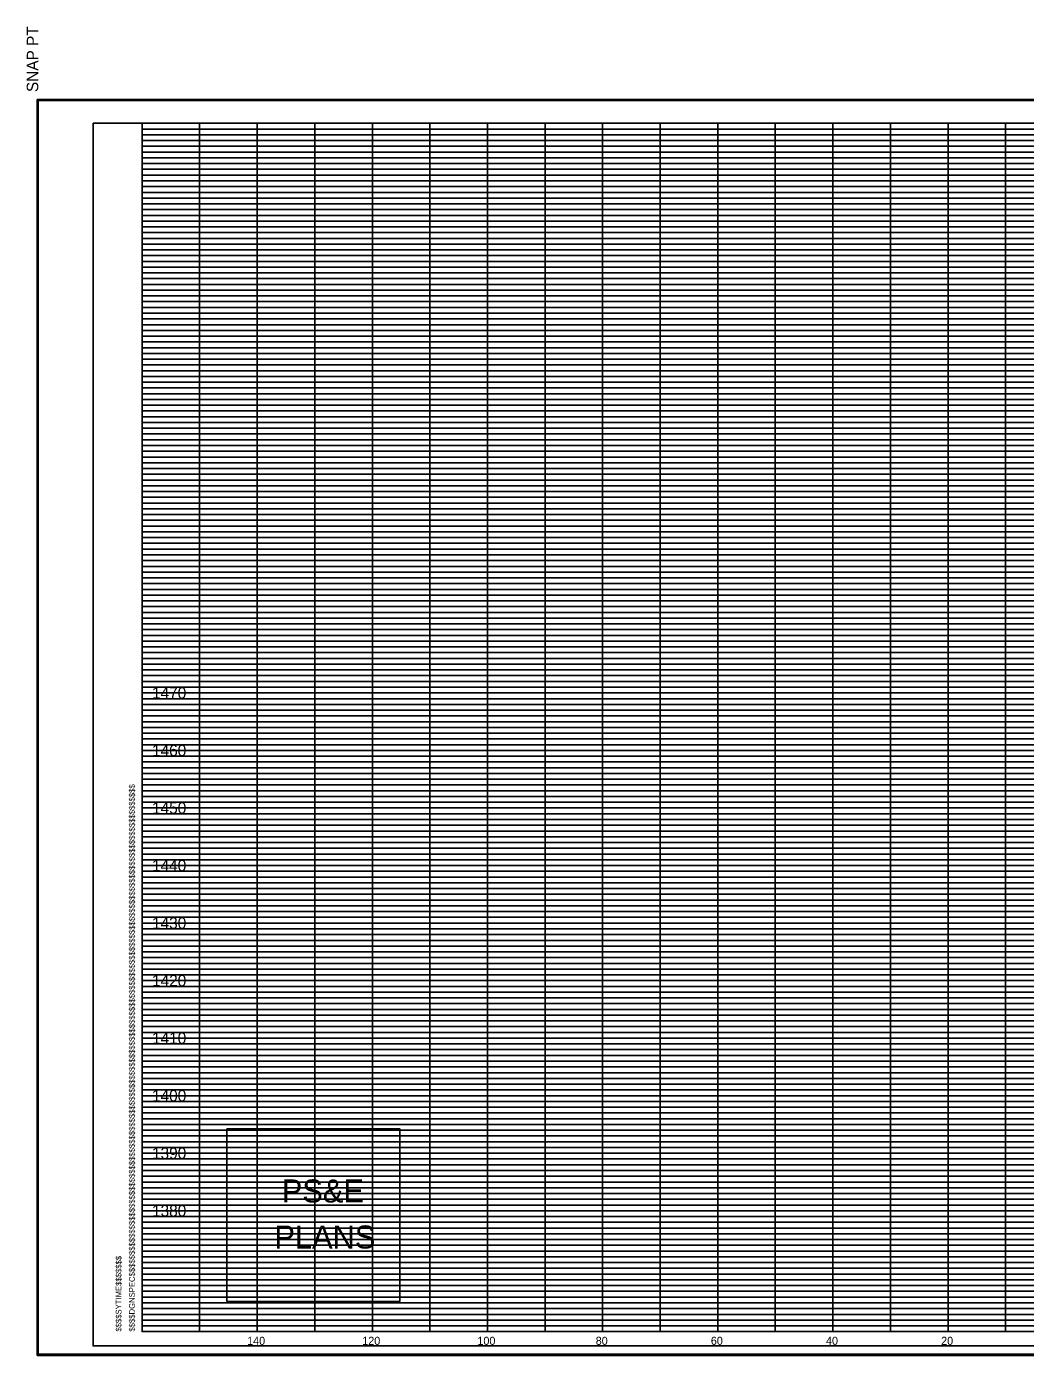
# Model space of a CAD drawing. Extents: x 980 to 2064, y 978 to 2267.
# Drawn here: x 1719.9 to 1893.4, y 1515.9 to 1746.8 of the extents above; entities that cross this region are included whole.
import ezdxf

# ---------------------------------------------------------------- set-up
doc = ezdxf.new("R2010")
doc.units = 0
for name, color, linetype in [('Default', 7, 'Continuous'), ('DESIGN - SHEET - Corner Text', 7, 'Continuous'), ('DESIGN - SHEET - Light Grid', 7, 'Continuous'), ('DESIGN - SHEET - Linework', 7, 'Continuous'), ('DESIGN - SHEET - Plot Shape', 7, 'Continuous')]:
    doc.layers.add(name, color=color, linetype=linetype)

# ---------------------------------------------------------------- blocks, each defined once
blk = doc.blocks.new('XSTSHT')
at = {"layer": 'DESIGN - SHEET - Light Grid'}
for p, q in [((0, 20.9), (8, 20.9)), ((0, 20.8), (8, 20.8)), ((8, 20.9), (16, 20.9)), ((8, 20.8), (16, 20.8)), ((0, 20.7), (8, 20.7)), ((0, 20.6), (8, 20.6)), ((8, 20.7), (16, 20.7)), ((8, 20.6), (16, 20.6)), ((0, 20.5), (8, 20.5)), ((0, 20.4), (8, 20.4)), ((8, 20.5), (16, 20.5)), ((8, 20.4), (16, 20.4)), ((0, 20.3), (8, 20.3)), ((0, 20.2), (8, 20.2)), ((0, 20.1), (8, 20.1)), ((8, 20.3), (16, 20.3)), ((8, 20.2), (16, 20.2)), ((8, 20.1), (16, 20.1)), ((0, 19.9), (8, 19.9)), ((8, 19.9), (16, 19.9)), ((0, 19.8), (8, 19.8)), ((0, 19.7), (8, 19.7)), ((8, 19.8), (16, 19.8)), ((8, 19.7), (16, 19.7)), ((0, 19.6), (8, 19.6)), ((0, 19.5), (8, 19.5)), ((0, 19.4), (8, 19.4)), ((8, 19.6), (16, 19.6)), ((8, 19.5), (16, 19.5)), ((8, 19.4), (16, 19.4)), ((0, 19.3), (8, 19.3)), ((0, 19.2), (8, 19.2)), ((8, 19.3), (16, 19.3)), ((8, 19.2), (16, 19.2)), ((0, 19.1), (8, 19.1)), ((8, 19.1), (16, 19.1)), ((0, 18.9), (8, 18.9)), ((0, 18.8), (8, 18.8)), ((8, 18.9), (16, 18.9)), ((8, 18.8), (16, 18.8)), ((0, 18.7), (8, 18.7)), ((0, 18.6), (8, 18.6)), ((0, 18.5), (8, 18.5)), ((8, 18.7), (16, 18.7)), ((8, 18.6), (16, 18.6)), ((8, 18.5), (16, 18.5)), ((0, 18.4), (8, 18.4)), ((0, 18.3), (8, 18.3)), ((8, 18.4), (16, 18.4)), ((8, 18.3), (16, 18.3)), ((0, 18.2), (8, 18.2)), ((0, 18.1), (8, 18.1)), ((8, 18.2), (16, 18.2)), ((8, 18.1), (16, 18.1)), ((0, 17.9), (8, 17.9)), ((0, 17.8), (8, 17.8)), ((8, 17.9), (16, 17.9)), ((8, 17.8), (16, 17.8)), ((0, 17.7), (8, 17.7)), ((0, 17.6), (8, 17.6)), ((8, 17.7), (16, 17.7)), ((8, 17.6), (16, 17.6)), ((0, 17.5), (8, 17.5)), ((0, 17.4), (8, 17.4)), ((8, 17.5), (16, 17.5)), ((8, 17.4), (16, 17.4)), ((0, 17.3), (8, 17.3)), ((0, 17.2), (8, 17.2)), ((0, 17.1), (8, 17.1)), ((8, 17.3), (16, 17.3)), ((8, 17.2), (16, 17.2)), ((8, 17.1), (16, 17.1)), ((0, 16.9), (8, 16.9)), ((8, 16.9), (16, 16.9)), ((0, 16.8), (8, 16.8)), ((0, 16.7), (8, 16.7)), ((8, 16.8), (16, 16.8)), ((8, 16.7), (16, 16.7)), ((0, 16.6), (8, 16.6)), ((0, 16.5), (8, 16.5)), ((0, 16.4), (8, 16.4)), ((8, 16.6), (16, 16.6)), ((8, 16.5), (16, 16.5)), ((8, 16.4), (16, 16.4)), ((0, 16.3), (8, 16.3)), ((0, 16.2), (8, 16.2)), ((8, 16.3), (16, 16.3)), ((8, 16.2), (16, 16.2)), ((0, 16.1), (8, 16.1)), ((8, 16.1), (16, 16.1)), ((0, 15.9), (8, 15.9)), ((0, 15.8), (8, 15.8)), ((8, 15.9), (16, 15.9)), ((8, 15.8), (16, 15.8)), ((0, 15.7), (8, 15.7)), ((0, 15.6), (8, 15.6)), ((0, 15.5), (8, 15.5)), ((8, 15.7), (16, 15.7)), ((8, 15.6), (16, 15.6)), ((8, 15.5), (16, 15.5)), ((0, 15.4), (8, 15.4)), ((0, 15.3), (8, 15.3)), ((8, 15.4), (16, 15.4)), ((8, 15.3), (16, 15.3)), ((0, 15.2), (8, 15.2)), ((0, 15.1), (8, 15.1)), ((8, 15.2), (16, 15.2)), ((8, 15.1), (16, 15.1)), ((0, 14.9), (8, 14.9)), ((0, 14.8), (8, 14.8)), ((8, 14.9), (16, 14.9)), ((8, 14.8), (16, 14.8)), ((0, 14.7), (8, 14.7)), ((0, 14.6), (8, 14.6)), ((8, 14.7), (16, 14.7)), ((8, 14.6), (16, 14.6)), ((0, 14.5), (8, 14.5)), ((0, 14.4), (8, 14.4)), ((8, 14.5), (16, 14.5)), ((8, 14.4), (16, 14.4)), ((0, 14.3), (8, 14.3)), ((0, 14.2), (8, 14.2)), ((0, 14.1), (8, 14.1)), ((8, 14.3), (16, 14.3)), ((8, 14.2), (16, 14.2)), ((8, 14.1), (16, 14.1)), ((0, 13.9), (8, 13.9)), ((8, 13.9), (16, 13.9)), ((0, 13.8), (8, 13.8)), ((0, 13.7), (8, 13.7)), ((8, 13.8), (16, 13.8)), ((8, 13.7), (16, 13.7)), ((0, 13.6), (8, 13.6)), ((0, 13.5), (8, 13.5)), ((0, 13.4), (8, 13.4)), ((8, 13.6), (16, 13.6)), ((8, 13.5), (16, 13.5)), ((8, 13.4), (16, 13.4)), ((0, 13.3), (8, 13.3)), ((0, 13.2), (8, 13.2)), ((8, 13.3), (16, 13.3)), ((8, 13.2), (16, 13.2)), ((0, 13.1), (8, 13.1)), ((8, 13.1), (16, 13.1)), ((0, 12.9), (8, 12.9)), ((0, 12.8), (8, 12.8)), ((8, 12.9), (16, 12.9)), ((8, 12.8), (16, 12.8)), ((0, 12.7), (8, 12.7)), ((0, 12.6), (8, 12.6)), ((0, 12.5), (8, 12.5)), ((8, 12.7), (16, 12.7)), ((8, 12.6), (16, 12.6)), ((8, 12.5), (16, 12.5)), ((0, 12.4), (8, 12.4)), ((0, 12.3), (8, 12.3)), ((8, 12.4), (16, 12.4)), ((8, 12.3), (16, 12.3)), ((0, 12.2), (8, 12.2)), ((0, 12.1), (8, 12.1)), ((8, 12.2), (16, 12.2)), ((8, 12.1), (16, 12.1)), ((0, 11.9), (8, 11.9)), ((0, 11.8), (8, 11.8)), ((8, 11.9), (16, 11.9)), ((8, 11.8), (16, 11.8)), ((0, 11.7), (8, 11.7)), ((0, 11.6), (8, 11.6)), ((8, 11.7), (16, 11.7)), ((8, 11.6), (16, 11.6)), ((0, 11.5), (8, 11.5)), ((0, 11.4), (8, 11.4)), ((8, 11.5), (16, 11.5)), ((8, 11.4), (16, 11.4)), ((0, 11.3), (8, 11.3)), ((0, 11.2), (8, 11.2)), ((0, 11.1), (8, 11.1)), ((8, 11.3), (16, 11.3)), ((8, 11.2), (16, 11.2)), ((8, 11.1), (16, 11.1)), ((0, 10.9), (8, 10.9)), ((8, 10.9), (16, 10.9)), ((0, 10.8), (8, 10.8)), ((0, 10.7), (8, 10.7)), ((8, 10.8), (16, 10.8)), ((8, 10.7), (16, 10.7)), ((0, 10.6), (8, 10.6)), ((0, 10.5), (8, 10.5)), ((0, 10.4), (8, 10.4)), ((8, 10.6), (16, 10.6)), ((8, 10.5), (16, 10.5)), ((8, 10.4), (16, 10.4)), ((0, 10.3), (8, 10.3)), ((0, 10.2), (8, 10.2)), ((8, 10.3), (16, 10.3)), ((8, 10.2), (16, 10.2)), ((0, 10.1), (8, 10.1)), ((8, 10.1), (16, 10.1)), ((0, 9.9), (8, 9.9)), ((0, 9.8), (8, 9.8)), ((0, 9.7), (8, 9.7)), ((8, 9.9), (16, 9.9)), ((8, 9.8), (16, 9.8)), ((8, 9.7), (16, 9.7)), ((0, 9.6), (8, 9.6)), ((0, 9.5), (8, 9.5)), ((8, 9.6), (16, 9.6)), ((8, 9.5), (16, 9.5)), ((0, 9.4), (8, 9.4)), ((0, 9.3), (8, 9.3)), ((8, 9.4), (16, 9.4)), ((8, 9.3), (16, 9.3)), ((0, 9.2), (8, 9.2)), ((0, 9.1), (8, 9.1)), ((8, 9.2), (16, 9.2)), ((8, 9.1), (16, 9.1)), ((0, 8.9), (8, 8.9)), ((0, 8.8), (8, 8.8)), ((8, 8.9), (16, 8.9)), ((8, 8.8), (16, 8.8)), ((0, 8.7), (8, 8.7)), ((0, 8.6), (8, 8.6)), ((8, 8.7), (16, 8.7)), ((8, 8.6), (16, 8.6)), ((0, 8.5), (8, 8.5)), ((0, 8.4), (8, 8.4)), ((8, 8.5), (16, 8.5)), ((8, 8.4), (16, 8.4)), ((0, 8.3), (8, 8.3)), ((0, 8.2), (8, 8.2)), ((0, 8.1), (8, 8.1)), ((8, 8.3), (16, 8.3)), ((8, 8.2), (16, 8.2)), ((8, 8.1), (16, 8.1)), ((0, 7.9), (8, 7.9)), ((8, 7.9), (16, 7.9)), ((0, 7.8), (8, 7.8)), ((0, 7.7), (8, 7.7)), ((8, 7.8), (16, 7.8)), ((8, 7.7), (16, 7.7)), ((0, 7.6), (8, 7.6)), ((0, 7.5), (8, 7.5)), ((0, 7.4), (8, 7.4)), ((8, 7.6), (16, 7.6)), ((8, 7.5), (16, 7.5)), ((8, 7.4), (16, 7.4)), ((0, 7.3), (8, 7.3)), ((0, 7.2), (8, 7.2)), ((8, 7.3), (16, 7.3)), ((8, 7.2), (16, 7.2)), ((0, 7.1), (8, 7.1)), ((8, 7.1), (16, 7.1)), ((0, 6.9), (8, 6.9)), ((0, 6.8), (8, 6.8)), ((0, 6.7), (8, 6.7)), ((8, 6.9), (16, 6.9)), ((8, 6.8), (16, 6.8)), ((8, 6.7), (16, 6.7)), ((0, 6.6), (8, 6.6)), ((0, 6.5), (8, 6.5)), ((8, 6.6), (16, 6.6)), ((8, 6.5), (16, 6.5)), ((0, 6.4), (8, 6.4)), ((0, 6.3), (8, 6.3)), ((8, 6.4), (16, 6.4)), ((8, 6.3), (16, 6.3)), ((0, 6.2), (8, 6.2)), ((0, 6.1), (8, 6.1)), ((8, 6.2), (16, 6.2)), ((8, 6.1), (16, 6.1)), ((0, 5.9), (8, 5.9)), ((0, 5.8), (8, 5.8)), ((8, 5.9), (16, 5.9)), ((8, 5.8), (16, 5.8)), ((0, 5.7), (8, 5.7)), ((0, 5.6), (8, 5.6)), ((8, 5.7), (16, 5.7)), ((8, 5.6), (16, 5.6)), ((0, 5.5), (8, 5.5)), ((0, 5.4), (8, 5.4)), ((8, 5.5), (16, 5.5)), ((8, 5.4), (16, 5.4)), ((0, 5.3), (8, 5.3)), ((0, 5.2), (8, 5.2)), ((0, 5.1), (8, 5.1)), ((8, 5.3), (16, 5.3)), ((8, 5.2), (16, 5.2)), ((8, 5.1), (16, 5.1)), ((0, 4.9), (8, 4.9)), ((8, 4.9), (16, 4.9)), ((0, 4.8), (8, 4.8)), ((0, 4.7), (8, 4.7)), ((8, 4.8), (16, 4.8)), ((8, 4.7), (16, 4.7)), ((0, 4.6), (8, 4.6)), ((0, 4.5), (8, 4.5)), ((0, 4.4), (8, 4.4)), ((8, 4.6), (16, 4.6)), ((8, 4.5), (16, 4.5)), ((8, 4.4), (16, 4.4)), ((0, 4.3), (8, 4.3)), ((0, 4.2), (8, 4.2)), ((8, 4.3), (16, 4.3)), ((8, 4.2), (16, 4.2)), ((0, 4.1), (8, 4.1)), ((8, 4.1), (16, 4.1)), ((0, 3.9), (8, 3.9)), ((0, 3.8), (8, 3.8)), ((0, 3.7), (8, 3.7)), ((8, 3.9), (16, 3.9)), ((8, 3.8), (16, 3.8)), ((8, 3.7), (16, 3.7)), ((0, 3.6), (8, 3.6)), ((0, 3.5), (8, 3.5)), ((8, 3.6), (16, 3.6)), ((8, 3.5), (16, 3.5)), ((0, 3.4), (8, 3.4)), ((0, 3.3), (8, 3.3)), ((8, 3.4), (16, 3.4)), ((8, 3.3), (16, 3.3)), ((0, 3.2), (8, 3.2)), ((0, 3.1), (8, 3.1)), ((8, 3.2), (16, 3.2)), ((8, 3.1), (16, 3.1)), ((0, 2.9), (8, 2.9)), ((0, 2.8), (8, 2.8)), ((8, 2.9), (16, 2.9)), ((8, 2.8), (16, 2.8)), ((0, 2.7), (8, 2.7)), ((0, 2.6), (8, 2.6)), ((8, 2.7), (16, 2.7)), ((8, 2.6), (16, 2.6)), ((0, 2.5), (8, 2.5)), ((0, 2.4), (8, 2.4)), ((8, 2.5), (16, 2.5)), ((8, 2.4), (16, 2.4)), ((0, 2.3), (8, 2.3)), ((0, 2.2), (8, 2.2)), ((0, 2.1), (8, 2.1)), ((8, 2.3), (16, 2.3)), ((8, 2.2), (16, 2.2)), ((8, 2.1), (16, 2.1)), ((0, 1.9), (8, 1.9)), ((8, 1.9), (16, 1.9)), ((0, 1.8), (8, 1.8)), ((0, 1.7), (8, 1.7)), ((8, 1.8), (16, 1.8)), ((8, 1.7), (16, 1.7)), ((0, 1.6), (8, 1.6)), ((0, 1.5), (8, 1.5)), ((0, 1.4), (8, 1.4)), ((8, 1.6), (16, 1.6)), ((8, 1.5), (16, 1.5)), ((8, 1.4), (16, 1.4)), ((0, 1.3), (8, 1.3)), ((0, 1.2), (8, 1.2)), ((8, 1.3), (16, 1.3)), ((8, 1.2), (16, 1.2)), ((0, 1.1), (8, 1.1)), ((8, 1.1), (16, 1.1)), ((0, 0.9), (8, 0.9)), ((0, 0.8), (8, 0.8)), ((0, 0.7), (8, 0.7)), ((8, 0.9), (16, 0.9)), ((8, 0.8), (16, 0.8)), ((8, 0.7), (16, 0.7)), ((0, 0.6), (8, 0.6)), ((0, 0.5), (8, 0.5)), ((8, 0.6), (16, 0.6)), ((8, 0.5), (16, 0.5)), ((0, 0.4), (8, 0.4)), ((0, 0.3), (8, 0.3)), ((8, 0.4), (16, 0.4)), ((8, 0.3), (16, 0.3)), ((0, 0.2), (8, 0.2)), ((0, 0.1), (8, 0.1)), ((8, 0.2), (16, 0.2)), ((8, 0.1), (16, 0.1))]:
    blk.add_line(p, q, dxfattribs=at)
at = {"layer": 'DESIGN - SHEET - Linework'}
for p, q in [((-1.823, -0.414), (-1.823, 21.414)), ((-1.823, 21.414), (32.217, 21.414)), ((1, 0), (1, 21)), ((2, 0), (2, 21)), ((3, 0), (3, 21)), ((4, 0), (4, 21)), ((5, 0), (5, 21)), ((6, 0), (6, 21)), ((7, 0), (7, 21)), ((8, 0), (8, 21)), ((9, 0), (9, 21)), ((10, 0), (10, 21)), ((11, 0), (11, 21)), ((12, 0), (12, 21)), ((13, 0), (13, 21)), ((14, 0), (14, 21)), ((15, 0), (15, 21)), ((0, 20), (28, 20)), ((0, 19), (32, 19)), ((0, 18), (32, 18)), ((0, 17), (32, 17)), ((0, 16), (32, 16)), ((0, 15), (32, 15)), ((0, 14), (32, 14)), ((0, 13), (32, 13)), ((0, 12), (32, 12)), ((0, 11), (32, 11)), ((0, 10), (32, 10)), ((0, 9), (32, 9)), ((0, 8), (32, 8)), ((0, 7), (32, 7)), ((0, 6), (32, 6)), ((0, 5), (32, 5)), ((0, 4), (32, 4)), ((0, 3), (32, 3)), ((0, 2), (32, 2)), ((0, 1), (32, 1)), ((-1.823, -0.414), (32.217, -0.414))]:
    blk.add_line(p, q, dxfattribs=at)
blk.add_lwpolyline([(0, 21), (0, 0), (32, 0), (32, 21), (0, 21)], dxfattribs=at)
at = {"layer": 'DESIGN - SHEET - Plot Shape'}
for points in [[(-1.803, 21.394), (32.197, 21.394), (32.197, -0.394), (-1.803, -0.394)], [(-0.85, 21), (32, 21), (32, -0.25), (-0.85, -0.25)]]:
    blk.add_lwpolyline(points, close=True, dxfattribs=at)
at = {"layer": 'DESIGN - SHEET - Corner Text'}
for s, height, p in [('  SNAP PT', 0.2, (-1.803, 21.394)), ('$$$$DGNSPEC$$$$$$$$$$$$$$$$$$$$$$$$$$$$$$$$$$$$$$$$$$$$$$$$$$$$$$$$$$$$$$$$$$$$$$$$$$$$$$$$$$$$$$$$$$$$$$$$$$$$$$$$$$$$$$$$$$$', 0.100002, (-0.126, 0)), ('$$$$SYTIME$$$$$$$', 0.1, (-0.358, 0))]:
    blk.add_text(s, height=height, rotation=90, dxfattribs=at).set_placement(p)

msp = doc.modelspace()

# ---------------------------------------------------------------- linework, layer by layer
at = {"layer": 'DESIGN - SHEET - Corner Text'}
msp.add_lwpolyline([(1754.75, 1555.26), (1754.75, 1525.26), (1784.75, 1525.26), (1784.75, 1555.26)], close=True, dxfattribs=at)

# ---------------------------------------------------------------- block references
at = {"layer": 'Default', "xscale": 10, "yscale": 10}
msp.add_blockref('XSTSHT', (1740, 1520), dxfattribs=at)

# ---------------------------------------------------------------- texts
at = {"layer": 'Default'}
for s, height, p in [('     1470     ', 2, (1738.01, 1630)), ('     1460     ', 2, (1738.01, 1620)), ('     1450     ', 2, (1738.01, 1610)), ('     1440     ', 2, (1738.01, 1600)), ('     1430     ', 2, (1738.01, 1590)), ('     1420     ', 2, (1738.01, 1580)), ('     1410     ', 2, (1738.01, 1570)), ('     1400     ', 2, (1738.01, 1560)), ('     1390     ', 2, (1738.01, 1550)), ('     1380     ', 2, (1738.01, 1540)), ('     140     ', 1.4, (1755.65, 1517.7)), ('     120     ', 1.4, (1775.65, 1517.7)), ('     100     ', 1.4, (1795.65, 1517.7)), ('     80     ', 1.4, (1816.2, 1517.7)), ('     60     ', 1.4, (1836.2, 1517.7)), ('     40     ', 1.4, (1856.2, 1517.7)), ('     20     ', 1.4, (1876.2, 1517.7))]:
    msp.add_text(s, height=height, dxfattribs=at).set_placement(p)
at = {"layer": 'DESIGN - SHEET - Corner Text'}
for s, p in [('PS&E', (1764.27, 1542.44)), ('PLANS', (1762.99, 1534.44))]:
    msp.add_text(s, height=4, dxfattribs=at).set_placement(p)

doc.saveas('drawing.dxf')
